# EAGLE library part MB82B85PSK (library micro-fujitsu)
MICROCONTROLLER/MEMORY DEVICE
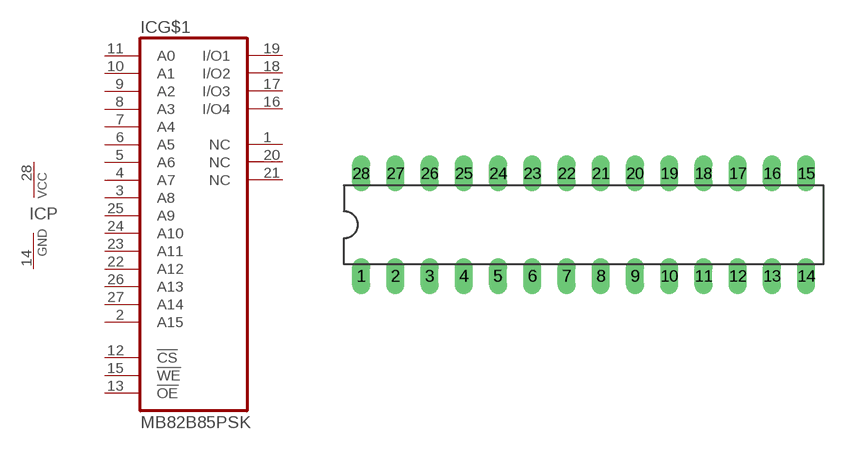
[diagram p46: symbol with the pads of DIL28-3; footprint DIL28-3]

Designator prefix IC; gates G$1=MB82B85 P=VCC-GND

## MB82B85PSK (OC_FARNELL: unknown; OC_NEWARK: unknown)  [DIL28-3]
1  G$1:NC  nc
2  G$1:A15  in
3  G$1:A8  in
4  G$1:A7  in
5  G$1:A6  in
6  G$1:A5  in
7  G$1:A4  in
8  G$1:A3  in
9  G$1:A2  in
10  G$1:A1  in
11  G$1:A0  in
12  G$1:!CS  in
13  G$1:!OE  in
14  P:GND  pwr
15  G$1:!WE  in
16  G$1:I/O4  nc
17  G$1:I/O3
18  G$1:I/O2
19  G$1:I/O1
20  G$1:NC  nc
21  G$1:NC  nc
22  G$1:A12  in
23  G$1:A11  in
24  G$1:A10  in
25  G$1:A9  in
26  G$1:A13  in
27  G$1:A14  in
28  P:VCC  pwr

## Footprint DIL28-3 (pad centres in mm)
Dual In Line Package Small
drill 0.813 long: 1 -16.51,-3.81; 2 -13.97,-3.81; 3 -11.43,-3.81; 4 -8.89,-3.81; 5 -6.35,-3.81; 6 -3.81,-3.81; 7 -1.27,-3.81; 8 1.27,-3.81; 9 3.81,-3.81; 10 6.35,-3.81; 11 8.89,-3.81; 12 11.43,-3.81; 13 13.97,-3.81; 14 16.51,-3.81; 15 16.51,3.81; 16 13.97,3.81; 17 11.43,3.81; 18 8.89,3.81; 19 6.35,3.81; 20 3.81,3.81; 21 1.27,3.81; 22 -1.27,3.81; 23 -3.81,3.81; 24 -6.35,3.81; 25 -8.89,3.81; 26 -11.43,3.81; 27 -13.97,3.81; 28 -16.51,3.81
